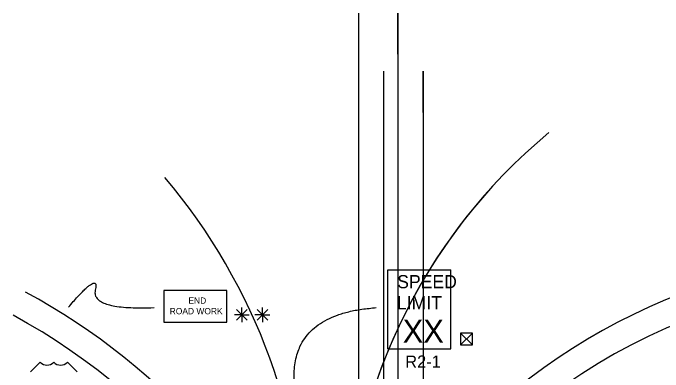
# Model space of a CAD drawing. Extents: x 16563 to 19504, y 6261 to 8279.
# Drawn here: x 16770.7 to 17165.8, y 8060.6 to 8278.5 of the extents above; entities that cross this region are included whole.
import ezdxf

# ---------------------------------------------------------------- set-up
doc = ezdxf.new("R2010")
doc.units = 0
for name, color, linetype in [('ALI_LEGAL_EX', 7, 'Continuous'), ('PAVT_EDGE_EX', 7, 'Continuous'), ('TRAFFIC_SIGNS_PR', 7, 'Continuous'), ('TYPICAL_EX', 7, 'Continuous'), ('TYPICAL_TEXT_DIMEN_PR', 7, 'Continuous')]:
    doc.layers.add(name, color=color, linetype=linetype)

msp = doc.modelspace()

# ---------------------------------------------------------------- linework, layer by layer
at = {"layer": 'ALI_LEGAL_EX'}
for p, q in [((16980.68, 8278.53), (16980.68, 7460.39)), ((17004.68, 8278.53), (17004.68, 7460.39)), ((16995.95, 8243.16), (16995.95, 7425.02)), ((17019.95, 8243.16), (17019.95, 7425.02))]:
    msp.add_line(p, q, dxfattribs=at)
for points in [[(17004.68, 8253.53), (17004.68, 8278.53)], [(17019.95, 8218.16), (17019.95, 8243.16)]]:
    msp.add_lwpolyline(points, dxfattribs=at)
for centre, radius, start, end in [((17313.01, 7943.78), 340, 129.5666, 180), ((16585.01, 7943.78), 364, 0, 40.1909), ((17313.01, 7943.78), 340, 137.516, 180)]:
    msp.add_arc(centre, radius, start, end, dxfattribs=at)
at = {"layer": 'PAVT_EDGE_EX'}
for centre, radius, start, end in [((17314.02, 7753.78), 380, 106.2376, 157.5011), ((16586.02, 7753.78), 404, 21.0961, 61.5719), ((17314.02, 7753.78), 364, 106.2376, 165.0045), ((16586.02, 7753.78), 388, 14.0482, 61.5719)]:
    msp.add_arc(centre, radius, start, end, dxfattribs=at)
at = {"layer": 'TRAFFIC_SIGNS_PR'}
for p, q in [((16998.46, 8122.54), (17036.86, 8122.54)), ((16998.46, 8074.54), (16998.46, 8122.54)), ((17036.86, 8074.54), (17036.86, 8122.54)), ((16998.46, 8074.54), (17036.86, 8074.54))]:
    msp.add_line(p, q, dxfattribs=at)
msp.add_lwpolyline([(16862.36, 8090.85), (16900.76, 8090.85), (16900.76, 8110.05), (16862.36, 8110.05)], close=True, dxfattribs=at)
at = {"layer": 'TYPICAL_EX'}
for p, q in [((16781.37, 8060.55), (16787.27, 8066.45)), ((16809.67, 8060.55), (16803.77, 8066.45))]:
    msp.add_line(p, q, dxfattribs=at)
for centre in [(16791.39, 8070.74), (16799.65, 8070.74)]:
    msp.add_arc(centre, 5.96, 226.1404, 313.8596, dxfattribs=at)
at = {"layer": 'TYPICAL_TEXT_DIMEN_PR'}
for p, q in [((16909.79, 8095.22), (16909.79, 8099.68)), ((16922.35, 8095.22), (16922.35, 8099.68)), ((16909.79, 8095.22), (16905.26, 8095.22)), ((16906.6, 8098.41), (16912.98, 8092.03)), ((16912.98, 8098.41), (16906.6, 8092.03)), ((16909.79, 8095.22), (16912.98, 8095.22)), ((16909.79, 8095.22), (16914.27, 8095.22)), ((16909.79, 8095.22), (16909.79, 8090.72)), ((16922.35, 8095.22), (16917.81, 8095.22)), ((16919.16, 8098.41), (16925.53, 8092.03)), ((16925.53, 8098.41), (16919.16, 8092.03)), ((16922.35, 8095.22), (16925.53, 8095.22)), ((16922.35, 8095.22), (16926.82, 8095.22)), ((16922.35, 8095.22), (16922.35, 8090.72)), ((17042.8, 8084.21), (17049.91, 8077.1)), ((17042.8, 8077.1), (17049.91, 8084.21))]:
    msp.add_line(p, q, dxfattribs=at)
msp.add_lwpolyline([(17042.8, 8084.21), (17042.8, 8077.1), (17049.91, 8077.1), (17049.91, 8084.21)], close=True, dxfattribs=at)
for points in [[(16804.46, 8099.89), (16823.67, 8122.49), (16817.82, 8098.21), (16856.52, 8099.61)], [(16948.4, 7945.64), (16979.76, 7955.08), (16994.7, 8014.55), (16941.5, 8020.27), (16941.6, 8096.03), (16991.53, 8099.63)]]:
    msp.add_open_spline(points, degree=2, dxfattribs=at)

# ---------------------------------------------------------------- texts
at = {"layer": 'TRAFFIC_SIGNS_PR'}
for s, height, p in [('SPEED', 8, (17004.23, 8111.4)), ('LIMIT', 8, (17004.07, 8098.6)), ('END', 3.832, (16877.36, 8101.98)), ('ROAD WORK', 3.832, (16865.97, 8095.59)), ('XX', 14.031, (17007.58, 8078.3)), ('R2-1', 7.44, (17009.14, 8063.1))]:
    msp.add_text(s, height=height, dxfattribs=at).set_placement(p)

doc.saveas('drawing.dxf')
